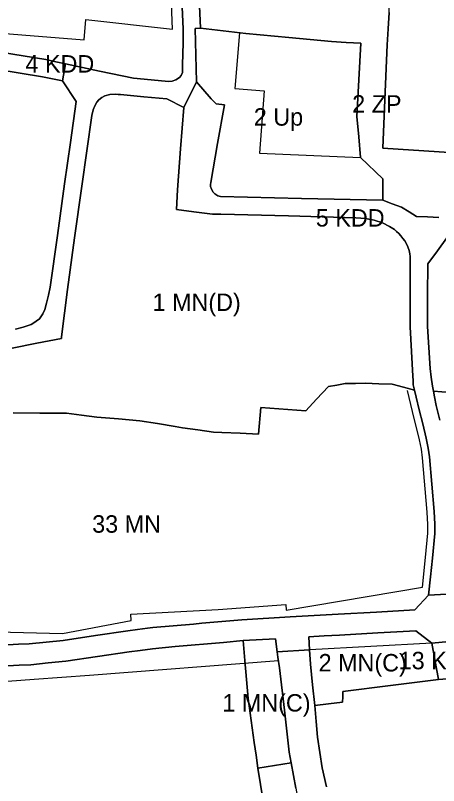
# Model space of a CAD drawing. Extents: x -294445 to -292055, y 21869 to 23693.
# Drawn here: x -293087.7 to -292845.3, y 22598.3 to 23039.5 of the extents above; entities that cross this region are included whole.
import ezdxf

# ---------------------------------------------------------------- set-up
doc = ezdxf.new("R2010")
doc.units = 0
for name, color, linetype in [('linie_rozgraniczajace', 7, 'Continuous'), ('linie_zabudowy_nieprzekraczalne', 7, 'Continuous'), ('oznaczenia_przeznaczen', 7, 'Continuous')]:
    doc.layers.add(name, color=color, linetype=linetype)

msp = doc.modelspace()

# ---------------------------------------------------------------- linework, layer by layer
at = {"layer": 'linie_rozgraniczajace'}
for points in [[(-292771.589, 22956.531), (-292877.28, 22963.509), (-292876.183, 22991.096), (-292874.759, 23022.559), (-292874.185, 23031.81), (-292873.61, 23041.06), (-292873.47, 23046.2), (-292897.16, 23048.645), (-292920.85, 23051.09), (-292951.805, 23054.48), (-292982.76, 23057.87), (-292984.75, 23073.22), (-292986.74, 23088.57), (-292990.18, 23114.94), (-292993.62, 23141.31), (-292996.45, 23158.64), (-292999.28, 23175.97), (-293001.304, 23186.662), (-293003.327, 23197.354), (-293003.749, 23202.623), (-293003.843, 23209.696)], [(-292992.732, 23057.008), (-292991.631, 23031.744), (-292991.69, 23024.337), (-292991.75, 23016.93), (-292991.914, 23011.811), (-292992.078, 23006.692), (-292992.681, 23005.107), (-292993.761, 23003.862), (-292995.719, 23002.503), (-292997.858, 23001.703), (-292999.946, 23001.659), (-293010.035, 23002.574), (-293020.124, 23003.489), (-293039.547, 23007.601), (-293058.97, 23011.713), (-293064.63, 23012.912), (-293070.29, 23014.11), (-293096.315, 23018.398)], [(-293020.124, 23003.489), (-293010.035, 23002.574), (-292999.946, 23001.659), (-292997.858, 23001.703), (-292995.719, 23002.503), (-292993.761, 23003.862), (-292992.681, 23005.107), (-292992.078, 23006.692), (-292991.914, 23011.811), (-292991.75, 23016.93), (-292991.69, 23024.337), (-292991.631, 23031.744), (-292992.732, 23057.008)], [(-292982.2, 23045.025), (-292981.64, 23032.18), (-292984.83, 23032.05), (-292984.445, 23016.74), (-292984.06, 23001.43), (-292991.32, 22986.68), (-293000.94, 22991.6), (-293014.206, 22992.874), (-293027.471, 22994.149), (-293028.867, 22994.225), (-293030.263, 22994.301), (-293033.633, 22994.073), (-293036.387, 22993.455), (-293038.241, 22992.528), (-293040.011, 22991.18), (-293041.023, 22989.804), (-293042.259, 22987.641), (-293043.13, 22985.422), (-293043.93, 22982.207), (-293046.78, 22961.904), (-293049.63, 22941.6), (-293053.778, 22912.05), (-293057.925, 22882.5), (-293059.583, 22868.95), (-293061.24, 22855.4), (-293061.28, 22854.448)], [(-292845.246, 22923.759), (-292851.578, 22924.027), (-292857.911, 22924.295), (-292862.195, 22926.918), (-292866.479, 22929.54), (-292871.889, 22931.557), (-292877.3, 22933.574), (-292877.25, 22945.85), (-292890.03, 22958.13), (-292891.045, 22969.815), (-292892.06, 22981.5), (-292890.98, 23002.5), (-292889.9, 23023.5), (-292898.285, 23024.02), (-292906.67, 23024.54), (-292931.145, 23026.77), (-292955.62, 23029), (-292968.63, 23030.59), (-292981.64, 23032.18), (-292982.2, 23045.025)], [(-292873.61, 23041.06), (-292874.185, 23031.81), (-292874.759, 23022.559), (-292876.183, 22991.096), (-292877.28, 22963.509), (-292771.589, 22956.531)], [(-293096.315, 23018.398), (-293070.29, 23014.11), (-293064.63, 23012.912), (-293058.97, 23011.713), (-293060.826, 23001.906), (-293072.139, 23004.28), (-293098.053, 23008.549)], [(-293087.721, 22859.716), (-293083.185, 22860.868), (-293078.632, 22862.444), (-293077.188, 22863.341), (-293075.744, 22864.238), (-293073.949, 22865.721), (-293071.919, 22868.608), (-293070.905, 22870.948), (-293069.838, 22874.58), (-293068.839, 22879.191), (-293067.84, 22883.802), (-293063.687, 22913.396), (-293059.533, 22942.99), (-293056.221, 22966.611), (-293052.908, 22990.232), (-293060.826, 23001.906), (-293058.97, 23011.713), (-293039.547, 23007.601), (-293020.124, 23003.489)], [(-293098.053, 23008.549), (-293072.139, 23004.28), (-293060.826, 23001.906), (-293052.908, 22990.232), (-293056.221, 22966.611), (-293059.533, 22942.99), (-293063.687, 22913.396), (-293067.84, 22883.802), (-293068.839, 22879.191), (-293069.838, 22874.58), (-293070.905, 22870.948), (-293071.919, 22868.608), (-293073.949, 22865.721), (-293075.744, 22864.238), (-293077.188, 22863.341), (-293078.632, 22862.444), (-293083.185, 22860.868), (-293087.721, 22859.716)], [(-292840.815, 22707.897), (-292850.987, 22707.279), (-292849.856, 22717.909), (-292848.725, 22728.539), (-292847.445, 22742.639), (-292847.457, 22747.954), (-292847.638, 22751.605), (-292847.82, 22755.255), (-292849.156, 22770.91), (-292850.492, 22786.564), (-292851.205, 22791.593), (-292851.795, 22794.441), (-292852.384, 22797.289), (-292854.387, 22805.435), (-292856.39, 22813.58), (-292858.105, 22820.795), (-292859.048, 22824.761), (-292859.799, 22827.923), (-292859.95, 22830.395), (-292860.08, 22832.78), (-292860.85, 22846.935), (-292861.62, 22861.09), (-292861.572, 22880.759), (-292861.524, 22900.428), (-292861.609, 22901.534), (-292861.695, 22902.641), (-292861.997, 22904.037), (-292862.298, 22905.434), (-292863.224, 22907.781), (-292864.643, 22910.326), (-292865.751, 22911.763), (-292866.858, 22913.2), (-292868.165, 22914.585), (-292869.405, 22915.676), (-292870.646, 22916.767), (-292873.376, 22918.635), (-292877.483, 22920.604), (-292882.298, 22922.189), (-292887.208, 22923.079), (-292889.871, 22923.286), (-292892.667, 22923.503), (-292931.341, 22924.603), (-292970.016, 22925.703), (-292974.78, 22925.7), (-292985.455, 22926.99), (-292995.446, 22928.343), (-292994.94, 22939.53), (-292993.13, 22963.105), (-292991.32, 22986.68), (-292984.06, 23001.43), (-292975.654, 22991.727), (-292972.712, 22988.794), (-292967.932, 22988.274), (-292971.892, 22966.011), (-292975.851, 22943.749), (-292975.887, 22942.6), (-292975.924, 22941.451), (-292975.356, 22939.88), (-292974.359, 22938.121), (-292973.423, 22937.163), (-292971.848, 22936.067), (-292970.272, 22935.771), (-292923.786, 22934.672), (-292877.3, 22933.574), (-292871.889, 22931.557), (-292866.479, 22929.54), (-292862.195, 22926.918), (-292857.911, 22924.295), (-292851.578, 22924.027), (-292845.246, 22923.759)], [(-293089.654, 22848.884), (-293075.467, 22851.666), (-293061.28, 22854.448), (-293061.24, 22855.4), (-293059.583, 22868.95), (-293057.925, 22882.5), (-293053.778, 22912.05), (-293049.63, 22941.6), (-293046.78, 22961.904), (-293043.93, 22982.207), (-293043.13, 22985.422), (-293042.259, 22987.641), (-293041.023, 22989.804), (-293040.011, 22991.18), (-293038.241, 22992.528), (-293036.387, 22993.455), (-293033.633, 22994.073), (-293030.263, 22994.301), (-293028.867, 22994.225), (-293027.471, 22994.149), (-293014.206, 22992.874), (-293000.94, 22991.6), (-292991.32, 22986.68), (-292993.13, 22963.105), (-292994.94, 22939.53), (-292995.446, 22928.343), (-292985.455, 22926.99), (-292974.78, 22925.7), (-292970.016, 22925.703), (-292931.341, 22924.603), (-292892.667, 22923.503), (-292889.871, 22923.286), (-292887.208, 22923.079), (-292882.298, 22922.189), (-292877.483, 22920.604), (-292873.376, 22918.635), (-292870.646, 22916.767), (-292869.405, 22915.676), (-292868.165, 22914.585), (-292866.858, 22913.2), (-292865.751, 22911.763), (-292864.643, 22910.326), (-292863.224, 22907.781), (-292862.298, 22905.434), (-292861.997, 22904.037), (-292861.695, 22902.641), (-292861.609, 22901.534), (-292861.524, 22900.428), (-292861.572, 22880.759), (-292861.62, 22861.09), (-292860.85, 22846.935), (-292860.08, 22832.78), (-292859.95, 22830.395), (-292859.799, 22827.923), (-292859.048, 22824.761), (-292865.429, 22826.45), (-292871.81, 22828.14), (-292879.455, 22828.46), (-292887.1, 22828.78), (-292892.915, 22828.65), (-292898.73, 22828.52), (-292903.545, 22827.695), (-292908.36, 22826.87), (-292915.17, 22819.59), (-292921.44, 22812.87), (-292947.04, 22814.95), (-292948.42, 22799.66), (-292958.905, 22800.103), (-292969.39, 22800.545), (-292974.24, 22800.75), (-292983.13, 22802.005), (-292992.02, 22803.26), (-292996.16, 22803.97), (-293006.255, 22805.635), (-293016.35, 22807.3), (-293028.725, 22808.325), (-293041.1, 22809.35), (-293049.76, 22810.44), (-293058.42, 22811.53), (-293073.705, 22811.635), (-293088.99, 22811.74)], [(-292840.509, 22912.145), (-292846.02, 22904.62), (-292851.532, 22897.095), (-292851.576, 22879.222), (-292851.619, 22861.35), (-292850.905, 22849.273), (-292850.191, 22837.196), (-292849.463, 22832.173), (-292848.735, 22827.15), (-292848.193, 22824.203), (-292847.603, 22821), (-292846.67, 22815.93), (-292844.631, 22807.623)], [(-292838.706, 22823.542), (-292848.193, 22824.203), (-292848.735, 22827.15), (-292849.463, 22832.173), (-292850.191, 22837.196), (-292850.905, 22849.273), (-292851.619, 22861.35), (-292851.576, 22879.222), (-292851.532, 22897.095), (-292846.02, 22904.62), (-292840.509, 22912.145)], [(-293061.28, 22854.448), (-293075.467, 22851.666), (-293089.654, 22848.884)], [(-293088.99, 22811.74), (-293073.705, 22811.635), (-293058.42, 22811.53), (-293049.76, 22810.44), (-293041.1, 22809.35), (-293028.725, 22808.325), (-293016.35, 22807.3), (-293006.255, 22805.635), (-292996.16, 22803.97), (-292992.02, 22803.26), (-292983.13, 22802.005), (-292974.24, 22800.75), (-292969.39, 22800.545), (-292958.905, 22800.103), (-292948.42, 22799.66), (-292947.04, 22814.95), (-292921.44, 22812.87), (-292915.17, 22819.59), (-292908.36, 22826.87), (-292903.545, 22827.695), (-292898.73, 22828.52), (-292892.915, 22828.65), (-292887.1, 22828.78), (-292879.455, 22828.46), (-292871.81, 22828.14), (-292865.429, 22826.45), (-292859.048, 22824.761), (-292858.105, 22820.795), (-292856.39, 22813.58), (-292854.387, 22805.435), (-292852.384, 22797.289), (-292851.795, 22794.441), (-292851.205, 22791.593), (-292850.492, 22786.564), (-292849.156, 22770.91), (-292847.82, 22755.255), (-292847.638, 22751.605), (-292847.457, 22747.954), (-292847.445, 22742.639), (-292848.725, 22728.539), (-292849.856, 22717.909), (-292850.987, 22707.279), (-292858.953, 22698.887), (-292880.846, 22697.706), (-292902.739, 22696.525), (-292930.404, 22694.927), (-292958.069, 22693.329), (-292969.499, 22692.291), (-292980.93, 22691.254), (-292985.744, 22690.845), (-292997.385, 22689.82), (-293009.027, 22688.795), (-293012.092, 22688.395), (-293017.702, 22687.663), (-293023.312, 22686.931), (-293041.797, 22684.203), (-293060.282, 22681.474), (-293070.044, 22680.498), (-293079.806, 22679.521), (-293085.91, 22679.252), (-293092.014, 22678.982)], [(-292844.631, 22807.623), (-292846.67, 22815.93), (-292847.603, 22821), (-292848.193, 22824.203), (-292838.706, 22823.542)], [(-293092.014, 22678.982), (-293085.91, 22679.252), (-293079.806, 22679.521), (-293070.044, 22680.498), (-293060.282, 22681.474), (-293041.797, 22684.203), (-293023.312, 22686.931), (-293017.702, 22687.663), (-293012.092, 22688.395), (-293009.027, 22688.795), (-292997.385, 22689.82), (-292985.744, 22690.845), (-292980.93, 22691.254), (-292969.499, 22692.291), (-292958.069, 22693.329), (-292930.404, 22694.927), (-292902.739, 22696.525), (-292880.846, 22697.706), (-292858.953, 22698.887), (-292850.987, 22707.279), (-292840.815, 22707.897)], [(-292839.224, 22680.815), (-292849.226, 22679.902), (-292858.248, 22686.908), (-292880.159, 22685.726), (-292902.07, 22684.544), (-292910.872, 22684.035), (-292919.675, 22683.527), (-292919.22, 22675.983), (-292937.725, 22674.947), (-292938.805, 22682.422), (-292957.18, 22681.36), (-292968.53, 22680.33), (-292979.88, 22679.3), (-292984.71, 22678.89), (-292996.216, 22677.877), (-293009.131, 22676.68), (-293016.15, 22675.764), (-293022.475, 22674.932), (-293040.641, 22672.246), (-293058.807, 22669.561), (-293068.876, 22668.555), (-293078.944, 22667.548), (-293085.501, 22667.258), (-293092.059, 22666.968)], [(-293092.059, 22666.968), (-293085.501, 22667.258), (-293078.944, 22667.548), (-293068.876, 22668.555), (-293058.807, 22669.561), (-293040.641, 22672.246), (-293022.475, 22674.932), (-293016.15, 22675.764), (-293009.131, 22676.68), (-292996.216, 22677.877), (-292984.71, 22678.89), (-292979.88, 22679.3), (-292968.53, 22680.33), (-292957.18, 22681.36), (-292956.29, 22669.92), (-292955.34, 22659.005), (-292954.39, 22648.09), (-292952.7, 22635.57), (-292951.01, 22623.05), (-292949.88, 22615.675), (-292948.75, 22608.3), (-292945.745, 22589.63)], [(-292927.04, 22596.744), (-292929.68, 22611.34), (-292930.85, 22617.42), (-292933.65, 22641.59), (-292936.45, 22665.76), (-292937.29, 22671.94), (-292937.725, 22674.947), (-292919.22, 22675.983), (-292918.732, 22667.898), (-292917.506, 22655.994), (-292916.28, 22644.09), (-292915.486, 22635.046), (-292914.693, 22626.001), (-292913.321, 22617.281), (-292911.95, 22608.56), (-292909.465, 22597.52)], [(-292909.465, 22597.52), (-292911.95, 22608.56), (-292913.321, 22617.281), (-292914.693, 22626.001), (-292915.486, 22635.046), (-292916.28, 22644.09), (-292908.27, 22645.05), (-292900.26, 22646.01), (-292900.245, 22649.115), (-292900.23, 22652.22), (-292872.79, 22655.63), (-292845.35, 22659.04), (-292835.339, 22659.903), (-292828.13, 22660.71), (-292817.95, 22662.24), (-292794.31, 22664.53), (-292770.67, 22666.82), (-292763.86, 22644.345), (-292757.05, 22621.87), (-292757.071, 22620.541), (-292757.32, 22604.665), (-292757.59, 22587.46)]]:
    msp.add_lwpolyline(points, dxfattribs=at)
for points in [[(-292984.83, 23032.05), (-292981.64, 23032.18), (-292968.63, 23030.59), (-292955.62, 23029), (-292931.145, 23026.77), (-292906.67, 23024.54), (-292898.285, 23024.02), (-292889.9, 23023.5), (-292890.98, 23002.5), (-292892.06, 22981.5), (-292891.045, 22969.815), (-292890.03, 22958.13), (-292877.25, 22945.85), (-292877.3, 22933.574), (-292923.786, 22934.672), (-292970.272, 22935.771), (-292971.848, 22936.067), (-292973.423, 22937.163), (-292974.359, 22938.121), (-292975.356, 22939.88), (-292975.924, 22941.451), (-292975.887, 22942.6), (-292975.851, 22943.749), (-292971.892, 22966.011), (-292967.932, 22988.274), (-292972.712, 22988.794), (-292975.654, 22991.727), (-292984.06, 23001.43), (-292984.445, 23016.74)], [(-292919.675, 22683.527), (-292910.872, 22684.035), (-292902.07, 22684.544), (-292880.159, 22685.726), (-292858.248, 22686.908), (-292849.226, 22679.902), (-292845.35, 22659.04), (-292872.79, 22655.63), (-292900.23, 22652.22), (-292900.245, 22649.115), (-292900.26, 22646.01), (-292908.27, 22645.05), (-292916.28, 22644.09), (-292917.506, 22655.994), (-292918.732, 22667.898), (-292919.22, 22675.983)], [(-292957.18, 22681.36), (-292938.805, 22682.422), (-292937.725, 22674.947), (-292937.29, 22671.94), (-292936.45, 22665.76), (-292933.65, 22641.59), (-292930.85, 22617.42), (-292929.68, 22611.34), (-292948.75, 22608.3), (-292949.88, 22615.675), (-292951.01, 22623.05), (-292952.7, 22635.57), (-292954.39, 22648.09), (-292955.34, 22659.005), (-292956.29, 22669.92)], [(-292849.226, 22679.902), (-292839.224, 22680.815), (-292837.282, 22670.359), (-292835.339, 22659.903), (-292845.35, 22659.04)], [(-292948.75, 22608.3), (-292929.68, 22611.34), (-292927.04, 22596.744), (-292924.4, 22582.147), (-292924.231, 22577.549), (-292924.849, 22574.683), (-292926.911, 22570.906), (-292940.132, 22555.546), (-292941.74, 22565.09), (-292943.07, 22572.98), (-292945.745, 22589.63)]]:
    msp.add_lwpolyline(points, close=True, dxfattribs=at)
at = {"layer": 'linie_zabudowy_nieprzekraczalne'}
for points in [[(-293285.056, 23113.767), (-293302.86, 22987.439), (-293306.681, 22966.878), (-293287.499, 22962.283), (-293291.884, 22942.735), (-293239.404, 22930.893), (-293235.383, 22945.584), (-293228.475, 22970.823), (-293209.126, 23043.154), (-293175.962, 23037.665), (-293174.572, 23037.441), (-293150.903, 23033.676), (-293048.406, 23025.552), (-293047.321, 23037.206), (-292997.632, 23031.638), (-292998.715, 23056.491)], [(-292959.425, 23029.465), (-292961.958, 22997.502), (-292945.153, 22996.17), (-292947.976, 22960.557), (-292890.03, 22958.13)], [(-293105.609, 22686.547), (-293060.776, 22685.477), (-293021.315, 22692.771), (-293021.635, 22696.501), (-292971.487, 22699.083), (-292932.829, 22701.968), (-292932.621, 22698.806), (-292854.521, 22711.869), (-292854.521, 22711.869), (-292854.521, 22711.869), (-292852.706, 22728.931), (-292851.445, 22742.815), (-292851.457, 22747.85), (-292851.811, 22754.986), (-292854.468, 22786.113), (-292855.148, 22790.906), (-292856.286, 22796.406), (-292860.278, 22812.64), (-292863.107, 22824.542)], [(-292849.226, 22679.902), (-292919.116, 22675.989)], [(-292936.995, 22669.768), (-293045.22, 22661.37), (-293076.999, 22659.077), (-293105.235, 22656.962), (-293155, 22661.193), (-293210.447, 22672.251), (-293214.074, 22656.903), (-293219.194, 22636.013), (-293219.194, 22636.013), (-293225.657, 22604.489), (-293225.657, 22604.489), (-293228.151, 22584.509)]]:
    msp.add_lwpolyline(points, dxfattribs=at)

# ---------------------------------------------------------------- texts
at = {"layer": 'oznaczenia_przeznaczen'}
for s, p in [('4 KDD', (-293081.92, 23006.713)), ('2 ZP', (-292894.775, 22983.762)), ('2 Up', (-292951.138, 22976.309)), ('5 KDD', (-292915.617, 22918.503)), ('1 MN(D)', (-293009.128, 22870.147)), ('33 MN', (-293043.72, 22743.145)), ('2 MN(C)', (-292914.027, 22663.668)), ('13 KDX', (-292868.146, 22664.915)), ('1 MN(C)', (-292969.154, 22640.696))]:
    msp.add_text(s, height=10, dxfattribs=at).set_placement(p)

doc.saveas('drawing.dxf')
